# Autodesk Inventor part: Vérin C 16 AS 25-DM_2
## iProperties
Shininess: 20.0
Angle Display Precision: 2
Document Length Units: 11269
Document Angle Units: 11279
Document Time Units: 11290
Document Mass Units: 11283
Document Length Units Precision: 3
Document Angle Units Precision: 2
Created: 2002-02
Part Number: Vérin C 16 AS 25-DM_2
Material: Par défaut
Document SubType Name: Modélisation
Designer: Administrateur
Density: 0.0
Volumn: 0.0
Area: 0.0
PropertySet Name: Model Information
Control State: 0
Master: False
Checked Out: False
Author: Administrateur
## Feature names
1. Base1
